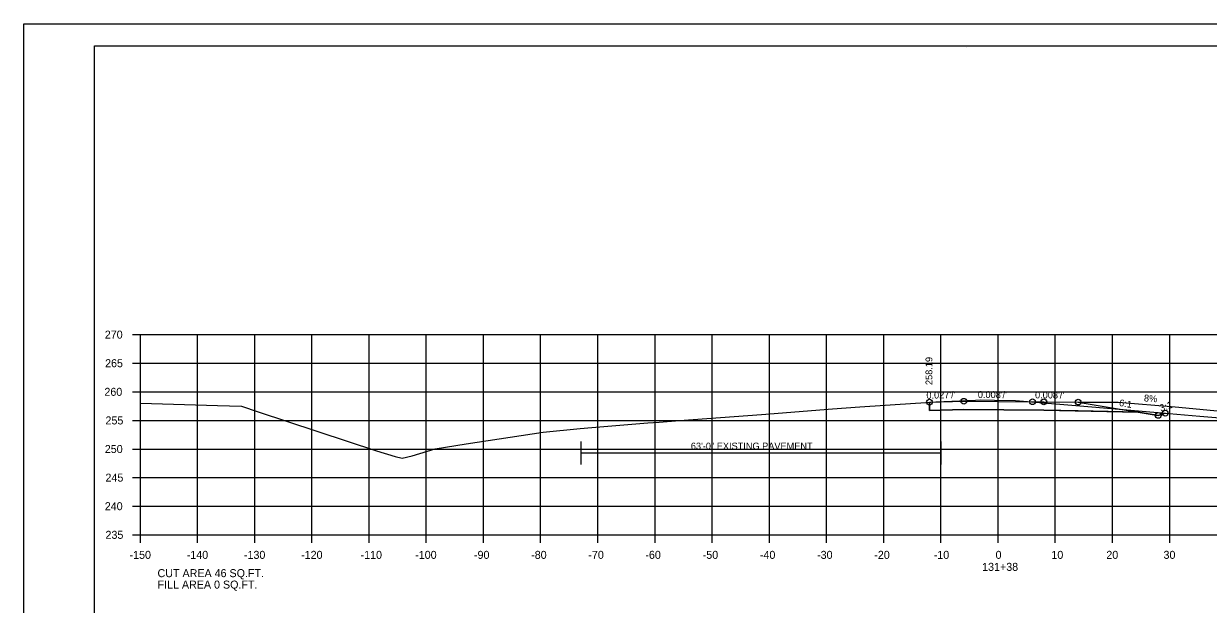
# Model space of a CAD drawing. Extents: x 1103485 to 1107180, y 2010593 to 2011873.
# Drawn here: x 1106846.8 to 1107053.9, y 2011344.7 to 2011446.2 of the extents above; entities that cross this region are included whole.
import ezdxf

# ---------------------------------------------------------------- set-up
doc = ezdxf.new("R2010")
doc.units = 0
for name, color, linetype in [('R_Alt Surface', 7, 'Continuous'), ('R_Axis', 7, 'Continuous'), ('R_Axis Annot', 7, 'Continuous'), ('R_Border', 7, 'Continuous'), ('R_Contours', 7, 'Continuous'), ('R_Dimension', 7, 'Continuous'), ('R_Drive', 7, 'Continuous'), ('R_Exist Surface', 7, 'Continuous'), ('R_Fin Surface', 7, 'Continuous'), ('R_Grid', 7, 'Continuous'), ('R_No Plot', 7, 'Continuous'), ('R_Proposed Const Limits', 7, 'Continuous'), ('R_Xsect Elev', 7, 'Continuous'), ('R_Xsect Slope', 7, 'Continuous')]:
    doc.layers.add(name, color=color, linetype=linetype)

msp = doc.modelspace()

# ---------------------------------------------------------------- linework, layer by layer
at = {"layer": 'R_Alt Surface'}
msp.add_lwpolyline([(1107005.18, 2011380.02), (1107005.18, 2011378.56), (1107011.18, 2011378.72), (1107025.18, 2011378.62), (1107041.64, 2011378.29)], dxfattribs=at)
at = {"layer": 'R_Axis'}
for p, q in [((1106865.78, 2011391.83), (1106867.18, 2011391.83)), ((1106867.18, 2011356.83), (1106867.18, 2011391.83)), ((1106865.78, 2011386.83), (1106867.18, 2011386.83)), ((1106865.78, 2011381.83), (1106867.18, 2011381.83)), ((1106865.78, 2011376.83), (1106867.18, 2011376.83)), ((1106865.78, 2011371.83), (1106867.18, 2011371.83)), ((1106865.78, 2011366.83), (1106867.18, 2011366.83)), ((1106865.78, 2011361.83), (1106867.18, 2011361.83)), ((1106865.78, 2011356.83), (1106867.18, 2011356.83)), ((1106867.18, 2011356.83), (1107167.18, 2011356.83)), ((1106867.18, 2011355.43), (1106867.18, 2011356.83)), ((1106877.18, 2011355.43), (1106877.18, 2011356.83)), ((1106887.18, 2011355.43), (1106887.18, 2011356.83)), ((1106897.18, 2011355.43), (1106897.18, 2011356.83)), ((1106907.18, 2011355.43), (1106907.18, 2011356.83)), ((1106917.18, 2011355.43), (1106917.18, 2011356.83)), ((1106927.18, 2011355.43), (1106927.18, 2011356.83)), ((1106937.18, 2011355.43), (1106937.18, 2011356.83)), ((1106947.18, 2011355.43), (1106947.18, 2011356.83)), ((1106957.18, 2011355.43), (1106957.18, 2011356.83)), ((1106967.18, 2011355.43), (1106967.18, 2011356.83)), ((1106977.18, 2011355.43), (1106977.18, 2011356.83)), ((1106987.18, 2011355.43), (1106987.18, 2011356.83)), ((1106997.18, 2011355.43), (1106997.18, 2011356.83)), ((1107007.18, 2011355.43), (1107007.18, 2011356.83)), ((1107017.18, 2011355.43), (1107017.18, 2011356.83)), ((1107027.18, 2011355.43), (1107027.18, 2011356.83)), ((1107037.18, 2011355.43), (1107037.18, 2011356.83)), ((1107047.18, 2011355.43), (1107047.18, 2011356.83))]:
    msp.add_line(p, q, dxfattribs=at)
at = {"layer": 'R_Border'}
for p, q in [((1106859.18, 2011442.29), (1107175.36, 2011442.29)), ((1106859.18, 2011236.83), (1106859.18, 2011442.29)), ((1107011.7, 2011442.03), (1107011.7, 2011442.03)), ((1107011.7, 2011442.03), (1107011.7, 2011442.03))]:
    msp.add_line(p, q, dxfattribs=at)
at = {"layer": 'R_Contours'}
msp.add_lwpolyline([(1107005.18, 2011380.01), (1107006.29, 2011380.06), (1107013.2, 2011380.4), (1107014.16, 2011380.44), (1107016.54, 2011380.4), (1107020.24, 2011380.33), (1107033.55, 2011379.19), (1107040.39, 2011378.62), (1107046.41, 2011378.1), (1107045.18, 2011377.7), (1107041.64, 2011378.29), (1107031.2, 2011378.5), (1107025.18, 2011378.62), (1107011.18, 2011378.72), (1107005.18, 2011378.56)], close=True, dxfattribs=at)
at = {"layer": 'R_Dimension'}
for p, q in [((1106944.18, 2011373.15), (1106944.18, 2011369.15)), ((1107007.18, 2011373.15), (1107007.18, 2011369.15)), ((1106944.18, 2011371.15), (1107007.18, 2011371.15))]:
    msp.add_line(p, q, dxfattribs=at)
at = {"layer": 'R_Drive'}
for p, q in [((1107031.18, 2011380.03), (1107038.18, 2011380.03)), ((1107038.18, 2011380.03), (1107048.15, 2011379.23)), ((1107048.15, 2011379.23), (1107079.85, 2011376.06))]:
    msp.add_line(p, q, dxfattribs=at)
at = {"layer": 'R_Exist Surface'}
msp.add_lwpolyline([(1106867.18, 2011379.87), (1106880.68, 2011379.46), (1106884.89, 2011379.3), (1106887.78, 2011378.36), (1106908.45, 2011371.53), (1106911.73, 2011370.52), (1106912.95, 2011370.22), (1106914.69, 2011370.64), (1106918.74, 2011371.89), (1106924.14, 2011372.71), (1106937.64, 2011374.79), (1106944.07, 2011375.41), (1106946.12, 2011375.61), (1106955.91, 2011376.38), (1106957.88, 2011376.54), (1106961.45, 2011376.8), (1106975.77, 2011377.84), (1106988.23, 2011378.84), (1106992.97, 2011379.22), (1107002.74, 2011379.85), (1107004.6, 2011379.98), (1107006.29, 2011380.06), (1107013.2, 2011380.4), (1107014.16, 2011380.44), (1107016.54, 2011380.4), (1107020.24, 2011380.33), (1107033.55, 2011379.19), (1107040.39, 2011378.62), (1107052.48, 2011377.58), (1107061.61, 2011376.83)], dxfattribs=at)
at = {"layer": 'R_Fin Surface'}
for points in [[(1107005.18, 2011380.02), (1107011.18, 2011380.18), (1107023.18, 2011380.09), (1107025.18, 2011380.08), (1107031.18, 2011380.03)], [(1107005.18, 2011380.02), (1107011.18, 2011380.18), (1107023.18, 2011380.09), (1107025.18, 2011380.08), (1107031.18, 2011380.03), (1107041.64, 2011378.29), (1107045.18, 2011377.7), (1107046.41, 2011378.1)]]:
    msp.add_lwpolyline(points, dxfattribs=at)
at = {"layer": 'R_Grid'}
for p, q in [((1106867.18, 2011391.83), (1107167.18, 2011391.83)), ((1106867.18, 2011356.83), (1106867.18, 2011391.83)), ((1106877.18, 2011356.83), (1106877.18, 2011391.83)), ((1106887.18, 2011356.83), (1106887.18, 2011391.83)), ((1106897.18, 2011356.83), (1106897.18, 2011391.83)), ((1106907.18, 2011356.83), (1106907.18, 2011391.83)), ((1106917.18, 2011356.83), (1106917.18, 2011391.83)), ((1106927.18, 2011356.83), (1106927.18, 2011391.83)), ((1106937.18, 2011356.83), (1106937.18, 2011391.83)), ((1106947.18, 2011356.83), (1106947.18, 2011391.83)), ((1106957.18, 2011356.83), (1106957.18, 2011391.83)), ((1106967.18, 2011356.83), (1106967.18, 2011391.83)), ((1106977.18, 2011356.83), (1106977.18, 2011391.83)), ((1106987.18, 2011356.83), (1106987.18, 2011391.83)), ((1106997.18, 2011356.83), (1106997.18, 2011391.83)), ((1107007.18, 2011356.83), (1107007.18, 2011391.83)), ((1107017.18, 2011356.83), (1107017.18, 2011391.83)), ((1107027.18, 2011356.83), (1107027.18, 2011391.83)), ((1107037.18, 2011356.83), (1107037.18, 2011391.83)), ((1107047.18, 2011356.83), (1107047.18, 2011391.83)), ((1106867.18, 2011386.83), (1107167.18, 2011386.83)), ((1106867.18, 2011381.83), (1107167.18, 2011381.83)), ((1106867.18, 2011376.83), (1107167.18, 2011376.83)), ((1106867.18, 2011371.83), (1107167.18, 2011371.83)), ((1106867.18, 2011366.83), (1107167.18, 2011366.83)), ((1106867.18, 2011361.83), (1107167.18, 2011361.83)), ((1106867.18, 2011356.83), (1107167.18, 2011356.83))]:
    msp.add_line(p, q, dxfattribs=at)
at = {"layer": 'R_No Plot'}
msp.add_line((1106846.78, 2011446.19), (1107180.12, 2011446.19), dxfattribs=at)
for points in [[(1106846.78, 2011446.19), (1107180.12, 2011446.19), (1107180.12, 2011232.85), (1106846.78, 2011232.85)], [(1107093.1, 2011442.29), (1107093.1, 2011432.41), (1107128.84, 2011432.41), (1107128.84, 2011429.49), (1107152.04, 2011429.49), (1107152.04, 2011405.16), (1107175.36, 2011405.16), (1107175.36, 2011236.83), (1106859.18, 2011236.83), (1106859.18, 2011442.29)]]:
    msp.add_lwpolyline(points, close=True, dxfattribs=at)
for centre in [(1107005.18, 2011380.02), (1107011.18, 2011380.18), (1107023.18, 2011380.09), (1107025.18, 2011380.08), (1107031.18, 2011380.03), (1107045.18, 2011377.7), (1107046.41, 2011378.1)]:
    msp.add_circle(centre, 0.5, dxfattribs=at)
at = {"layer": 'R_Proposed Const Limits'}
msp.add_lwpolyline([(1107031.18, 2011380.03), (1107045.18, 2011377.7), (1107046.41, 2011378.1)], dxfattribs=at)

# ---------------------------------------------------------------- texts
at = {"layer": 'R_Axis Annot'}
for s, p in [('270', (1106860.96, 2011391.13)), ('265', (1106861.01, 2011386.13)), ('260', (1106860.89, 2011381.13)), ('255', (1106861.08, 2011376.13)), ('250', (1106860.96, 2011371.13)), ('245', (1106861.08, 2011366.13)), ('240', (1106860.96, 2011361.13)), ('235', (1106861.08, 2011356.13)), ('-150', (1106865.29, 2011352.63)), ('-140', (1106875.29, 2011352.63)), ('-130', (1106885.29, 2011352.63)), ('-120', (1106895.29, 2011352.63)), ('-110', (1106905.69, 2011352.63)), ('-100', (1106915.24, 2011352.63)), ('-90', (1106925.52, 2011352.63)), ('-80', (1106935.52, 2011352.63)), ('-70', (1106945.52, 2011352.63)), ('-60', (1106955.49, 2011352.63)), ('-50', (1106965.52, 2011352.63)), ('-40', (1106975.52, 2011352.63)), ('-30', (1106985.52, 2011352.63)), ('-20', (1106995.52, 2011352.63)), ('-10', (1107005.92, 2011352.63)), ('0', (1107016.73, 2011352.63)), ('10', (1107026.49, 2011352.63)), ('20', (1107036.1, 2011352.63)), ('30', (1107046.1, 2011352.63)), ('CUT AREA 46 SQ.FT.', (1106870.18, 2011349.43)), ('131+38', (1107014.38, 2011350.53)), ('FILL AREA 0 SQ.FT.', (1106870.18, 2011347.43))]:
    msp.add_text(s, height=1.4, dxfattribs=at).set_placement(p)
at = {"layer": 'R_Dimension'}
msp.add_text('63\'-0" EXISTING PAVEMENT', height=1.2, dxfattribs=at).set_placement((1106963.44, 2011371.75))
at = {"layer": 'R_Drive'}
msp.add_text('8%', height=1.2, rotation=355.426, dxfattribs=at).set_placement((1107042.64, 2011380.18))
at = {"layer": 'R_Xsect Elev'}
msp.add_text('258.19', height=1.2, rotation=90, dxfattribs=at).set_placement((1107005.68, 2011383.02))
at = {"layer": 'R_Xsect Slope'}
for s, rotation, p in [("0.027'/'", 1.5466, (1107004.65, 2011380.61)), ("0.008'/'", 359.5581, (1107013.63, 2011380.76)), ("0.008'/'", 359.5581, (1107023.63, 2011380.69)), ('6:1', 350.5358, (1107038.27, 2011379.36)), ('3:1', 18.4332, (1107045.64, 2011378.37))]:
    msp.add_text(s, height=1.2, rotation=rotation, dxfattribs=at).set_placement(p)

doc.saveas('drawing.dxf')
